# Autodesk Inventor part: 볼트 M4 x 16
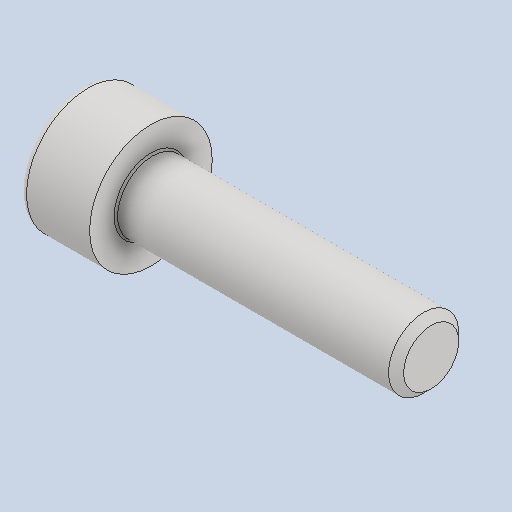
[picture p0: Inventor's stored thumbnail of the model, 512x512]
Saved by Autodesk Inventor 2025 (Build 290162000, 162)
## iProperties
Created: 2024-07
Part Number: 볼트 M4 x 16
Material: 스테인리스강
Description: 6각 소켓 머리 캡 나사
Document SubType Name: Modeling
Designer: anfro
Density: 8.08 g/cm^3
Appearance: 기본값
Author: jhkim
Sending System: Autodesk Inventor 2025
Preprocessor: ST-DEVELOPER v20
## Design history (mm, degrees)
feature "Solid1"
node "솔리드1"
